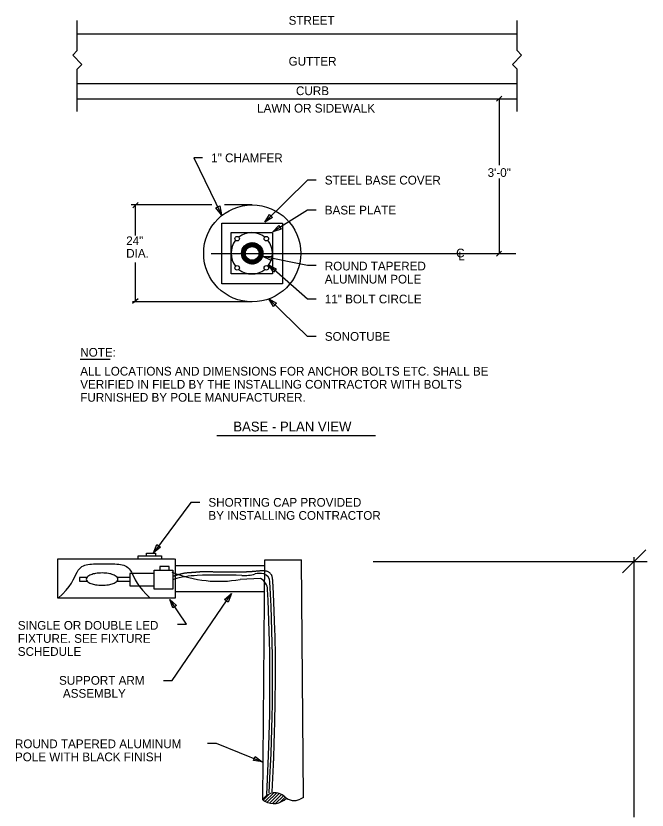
# Model space of a CAD drawing. Extents: x 10112 to 10168, y 10050 to 10179.
# Drawn here: x 10120 to 10168.3, y 10118.7 to 10179.4 of the extents above; entities that cross this region are included whole.
import ezdxf

# ---------------------------------------------------------------- set-up
doc = ezdxf.new("R2010")
doc.units = 0
for name, color, linetype in [('G-ANNO-TEXT', 7, 'Continuous'), ('G-DETL-LINE', 7, 'Continuous'), ('G-DETL-OTLN', 7, 'Continuous'), ('G-DETL-PATT', 7, 'Continuous')]:
    doc.layers.add(name, color=color, linetype=linetype)

msp = doc.modelspace()

# ---------------------------------------------------------------- linework, layer by layer
at = {"layer": 'G-ANNO-TEXT'}
for p, q in [((10157.184, 10173.296), (10156.792, 10172.903)), ((10156.982, 10173.091), (10156.982, 10168.015)), ((10134.303, 10168.58), (10133.637, 10168.58)), ((10133.637, 10168.58), (10135.77, 10164.228)), ((10156.982, 10166.989), (10156.982, 10161.238)), ((10142.321, 10166.873), (10139.076, 10163.664)), ((10142.988, 10166.873), (10142.321, 10166.873)), ((10129.376, 10165.155), (10128.984, 10164.763)), ((10135.018, 10164.983), (10128.862, 10164.983)), ((10129.165, 10164.974), (10129.165, 10162.651)), ((10138.105, 10164.983), (10135.995, 10164.983)), ((10142.321, 10164.581), (10139.677, 10162.912)), ((10142.988, 10164.581), (10142.321, 10164.581)), ((10158.264, 10161.238), (10134.973, 10161.238)), ((10142.321, 10160.342), (10138.925, 10161.033)), ((10157.173, 10161.439), (10156.781, 10161.047)), ((10129.165, 10160.568), (10129.165, 10157.551)), ((10142.321, 10157.781), (10139.339, 10160.394)), ((10142.988, 10160.342), (10142.321, 10160.342)), ((10129.376, 10157.792), (10128.954, 10157.43)), ((10138.105, 10157.562), (10128.959, 10157.562)), ((10142.321, 10154.92), (10139.376, 10157.8)), ((10142.988, 10157.781), (10142.321, 10157.781)), ((10142.988, 10154.92), (10142.321, 10154.92)), ((10124.964, 10153.175), (10127.256, 10153.175)), ((10135.397, 10147.346), (10147.527, 10147.346)), ((10133.424, 10142.217), (10130.559, 10138.375)), ((10134.091, 10142.217), (10133.424, 10142.217)), ((10166.424, 10136.833), (10168.195, 10138.603)), ((10167.31, 10118.148), (10167.31, 10138.036)), ((10147.356, 10137.718), (10168.298, 10137.718)), ((10133.07, 10132.903), (10131.817, 10134.81)), ((10131.983, 10128.612), (10136.511, 10135.252)), ((10132.403, 10132.903), (10133.07, 10132.903)), ((10131.316, 10128.612), (10131.983, 10128.612)), ((10134.682, 10123.803), (10135.348, 10123.803)), ((10135.348, 10123.803), (10138.879, 10122.387))]:
    msp.add_line(p, q, dxfattribs=at)
for points in [[(10135.626, 10164.9), (10135.77, 10164.228), (10135.326, 10164.753)], [(10139.667, 10164.014), (10139.076, 10163.664), (10139.433, 10164.251)], [(10140.33, 10163.127), (10139.677, 10162.912), (10140.152, 10163.409)], [(10139.545, 10160.736), (10138.925, 10161.033), (10139.612, 10161.063)], [(10139.73, 10159.829), (10139.339, 10160.394), (10139.95, 10160.08)], [(10139.736, 10157.214), (10139.376, 10157.8), (10139.969, 10157.453)], [(10131.092, 10138.81), (10130.559, 10138.375), (10130.824, 10139.009)], [(10132.044, 10134.161), (10131.817, 10134.81), (10132.322, 10134.345)], [(10135.997, 10134.795), (10136.511, 10135.252), (10136.273, 10134.607)], [(10138.322, 10122.79), (10138.879, 10122.387), (10138.198, 10122.481)]]:
    msp.add_lwpolyline(points, close=True, dxfattribs=at)
at = {"layer": 'G-DETL-LINE'}
for p, q in [((10124.724, 10178.065), (10158.366, 10178.065)), ((10124.724, 10174.271), (10158.366, 10174.271)), ((10124.724, 10173.091), (10158.366, 10173.091)), ((10136.49, 10159.697), (10136.49, 10162.861)), ((10136.49, 10162.861), (10139.654, 10162.861)), ((10139.654, 10162.861), (10139.654, 10159.697)), ((10137.284, 10161.303), (10138.074, 10162.093)), ((10137.284, 10161.251), (10138.126, 10162.093)), ((10137.287, 10161.201), (10138.176, 10162.09)), ((10137.288, 10161.36), (10138.018, 10162.089)), ((10137.297, 10161.421), (10137.956, 10162.08)), ((10137.893, 10161.756), (10138.222, 10162.085)), ((10137.973, 10161.783), (10138.267, 10162.077)), ((10137.292, 10161.155), (10137.621, 10161.484)), ((10137.312, 10161.488), (10137.889, 10162.064)), ((10137.338, 10161.566), (10137.811, 10162.039)), ((10137.382, 10161.662), (10137.715, 10161.995)), ((10138.038, 10161.796), (10138.309, 10162.068)), ((10138.094, 10161.8), (10138.35, 10162.056)), ((10138.145, 10161.799), (10138.389, 10162.042)), ((10138.191, 10161.793), (10138.426, 10162.028)), ((10138.234, 10161.784), (10138.462, 10162.011)), ((10138.275, 10161.772), (10138.497, 10161.994)), ((10138.312, 10161.757), (10138.53, 10161.975)), ((10138.348, 10161.741), (10138.562, 10161.954)), ((10138.381, 10161.722), (10138.592, 10161.933)), ((10138.412, 10161.701), (10138.622, 10161.91)), ((10138.442, 10161.678), (10138.65, 10161.886)), ((10138.47, 10161.653), (10138.677, 10161.861)), ((10138.495, 10161.627), (10138.703, 10161.834)), ((10138.519, 10161.599), (10138.728, 10161.807)), ((10138.541, 10161.569), (10138.751, 10161.779)), ((10138.562, 10161.537), (10138.773, 10161.748)), ((10138.58, 10161.503), (10138.794, 10161.717)), ((10138.595, 10161.466), (10138.814, 10161.685)), ((10138.609, 10161.428), (10138.833, 10161.652)), ((10138.62, 10161.386), (10138.85, 10161.616)), ((10138.628, 10161.342), (10138.866, 10161.58)), ((10138.631, 10161.241), (10138.893, 10161.502)), ((10138.632, 10161.294), (10138.88, 10161.542)), ((10137.3, 10161.11), (10137.594, 10161.404)), ((10137.31, 10161.068), (10137.581, 10161.339)), ((10137.321, 10161.027), (10137.577, 10161.283)), ((10137.334, 10160.988), (10137.578, 10161.232)), ((10137.349, 10160.951), (10137.584, 10161.186)), ((10137.365, 10160.915), (10137.593, 10161.143)), ((10137.383, 10160.88), (10137.605, 10161.102)), ((10137.402, 10160.847), (10137.62, 10161.065)), ((10137.423, 10160.815), (10137.636, 10161.029)), ((10137.444, 10160.785), (10137.655, 10160.996)), ((10137.467, 10160.755), (10137.676, 10160.965)), ((10137.491, 10160.727), (10137.699, 10160.935)), ((10137.516, 10160.7), (10137.723, 10160.907)), ((10137.542, 10160.674), (10137.75, 10160.882)), ((10137.57, 10160.65), (10137.778, 10160.858)), ((10138.052, 10160.453), (10138.924, 10161.325)), ((10138.103, 10160.452), (10138.926, 10161.275)), ((10138.157, 10160.453), (10138.924, 10161.22)), ((10138.214, 10160.459), (10138.918, 10161.162)), ((10138.278, 10160.47), (10138.907, 10161.099)), ((10138.349, 10160.489), (10138.888, 10161.028)), ((10138.432, 10160.52), (10138.858, 10160.946)), ((10138.569, 10161.022), (10138.92, 10161.373)), ((10138.608, 10161.113), (10138.913, 10161.418)), ((10138.624, 10161.182), (10138.904, 10161.461)), ((10137.599, 10160.626), (10137.808, 10160.836)), ((10137.628, 10160.604), (10137.84, 10160.815)), ((10137.659, 10160.582), (10137.874, 10160.797)), ((10137.692, 10160.563), (10137.911, 10160.781)), ((10137.726, 10160.544), (10137.949, 10160.768)), ((10137.761, 10160.527), (10137.991, 10160.757)), ((10137.797, 10160.511), (10138.035, 10160.749)), ((10137.835, 10160.497), (10138.083, 10160.745)), ((10137.874, 10160.484), (10138.136, 10160.746)), ((10137.916, 10160.473), (10138.195, 10160.753)), ((10137.959, 10160.465), (10138.264, 10160.769)), ((10138.004, 10160.458), (10138.355, 10160.808)), ((10138.542, 10160.577), (10138.799, 10160.834)), ((10139.654, 10159.697), (10136.49, 10159.697)), ((10129.388, 10137.873), (10129.388, 10138.143)), ((10129.388, 10138.143), (10131.173, 10138.143)), ((10130.028, 10138.177), (10130.028, 10138.345)), ((10130.028, 10138.345), (10130.701, 10138.345)), ((10130.701, 10138.345), (10130.701, 10138.143)), ((10131.173, 10138.143), (10131.173, 10137.873)), ((10131.745, 10137.334), (10131.038, 10137.334)), ((10131.038, 10137.334), (10131.038, 10137.098)), ((10131.745, 10137.031), (10131.745, 10137.334)), ((10130.6, 10136.795), (10128.748, 10136.795)), ((10128.748, 10136.795), (10128.748, 10135.852)), ((10130.6, 10135.582), (10130.6, 10137.031)), ((10130.6, 10137.031), (10132.048, 10137.031)), ((10132.048, 10137.031), (10132.048, 10135.582)), ((10124.909, 10136.492), (10124.909, 10136.189)), ((10125.464, 10136.492), (10124.909, 10136.492)), ((10124.909, 10136.189), (10125.499, 10136.189)), ((10127.754, 10136.189), (10128.748, 10136.189)), ((10128.714, 10136.492), (10127.789, 10136.492)), ((10128.748, 10135.852), (10130.6, 10135.852)), ((10132.048, 10135.582), (10130.6, 10135.582))]:
    msp.add_line(p, q, dxfattribs=at)
for points in [[(10123.281, 10134.894), (10123.603, 10135.195), (10123.881, 10135.501), (10124.104, 10135.788), (10124.282, 10136.055), (10124.423, 10136.302), (10124.537, 10136.525), (10124.633, 10136.722), (10124.721, 10136.893), (10124.809, 10137.036), (10124.9, 10137.154), (10124.994, 10137.248), (10125.092, 10137.323), (10125.196, 10137.38), (10125.306, 10137.424), (10125.423, 10137.456), (10125.549, 10137.48), (10125.684, 10137.499), (10125.827, 10137.513), (10125.978, 10137.523), (10126.134, 10137.529), (10126.295, 10137.534), (10126.46, 10137.536), (10126.627, 10137.536), (10126.795, 10137.536), (10126.963, 10137.536), (10127.13, 10137.536), (10127.295, 10137.534), (10127.456, 10137.529), (10127.612, 10137.523), (10127.763, 10137.513), (10127.906, 10137.499), (10128.041, 10137.48), (10128.167, 10137.456), (10128.284, 10137.424), (10128.394, 10137.38), (10128.498, 10137.323), (10128.596, 10137.248), (10128.69, 10137.154), (10128.781, 10137.036), (10128.869, 10136.893), (10128.957, 10136.722), (10129.053, 10136.525), (10129.167, 10136.302), (10129.308, 10136.055), (10129.486, 10135.788), (10129.709, 10135.501), (10129.987, 10135.195), (10130.309, 10134.894)], [(10138.745, 10136.394), (10137.186, 10136.334)], [(10139.225, 10119.892), (10139.345, 10122.833)], [(10139.405, 10120.012), (10139.465, 10121.153)]]:
    msp.add_lwpolyline(points, dxfattribs=at)
for radius in [0.821, 0.528]:
    msp.add_circle((10138.105, 10161.272), radius, dxfattribs=at)
for centre, radius, start, end in [((10138.072, 10161.279), 1.582, 51.23099, 128.76901), ((10138.072, 10161.279), 1.582, 141.23099, 218.76901), ((10138.072, 10161.279), 1.582, 321.23099, 38.76901), ((10138.072, 10161.279), 1.582, 231.23099, 308.76901), ((10126.096, 10135.852), 0.9, 111.26491, 133.21513), ((10126.415, 10135.031), 1.781, 99.15747, 111.26491), ((10126.627, 10133.72), 3.108, 90, 99.15747), ((10126.627, 10133.72), 3.108, 80.84253, 90), ((10126.838, 10135.031), 1.781, 68.73509, 80.84253), ((10127.157, 10135.852), 0.9, 46.78487, 68.73509), ((10134.18, 10129.33), 7.31, 92.30024, 106.63696), ((10135.596, 10094.074), 42.594, 87.69976, 92.30024), ((10137.437, 10139.908), 3.277, 267.69976, 285.72889), ((10138.655, 10135.582), 1.217, 74.27111, 105.72889), ((10138.806, 10136.119), 0.66, 3.01076, 74.2711), ((10125.621, 10136.357), 0.207, 133.21513, 180), ((10125.621, 10136.357), 0.207, 180, 226.78487), ((10126.096, 10136.862), 0.9, 226.78487, 248.73509), ((10126.415, 10137.683), 1.781, 248.73509, 260.84253), ((10126.838, 10137.683), 1.781, 279.15747, 291.26491), ((10127.157, 10136.862), 0.9, 291.26491, 313.21513), ((10127.632, 10136.357), 0.207, 360, 46.78487), ((10127.632, 10136.357), 0.207, 313.21513, 0), ((10138.283, 10135.503), 1.003, 2.85862, 62.57663), ((10126.627, 10138.994), 3.108, 260.84253, 270), ((10126.627, 10138.994), 3.108, 270, 279.15747)]:
    msp.add_arc(centre, radius, start, end, dxfattribs=at)
for centre, major_axis, ratio, start_param, end_param in [((10135.552, 10329.219), (0, 193.028), 0.220109, 3.057124, 3.180061), ((9992.817, 10128.653), (146.851, 0), 0.972426, 6.230638, 6.335733), ((9994.416, 10128.553), (145.049, 0), 0.967642, 6.242419, 6.333078)]:
    msp.add_ellipse(centre, major_axis=major_axis, ratio=ratio, start_param=start_param, end_param=end_param, dxfattribs=at)
msp.add_open_spline([(10139.629, 10120.085), (10139.719, 10121.649), (10139.809, 10124.386), (10139.869, 10127.153), (10139.899, 10130.762), (10139.779, 10134.101), (10139.719, 10135.575), (10139.689, 10136.082), (10139.659, 10136.503), (10139.569, 10136.713), (10139.358, 10136.924), (10138.968, 10137.014), (10137.795, 10136.894), (10136.683, 10136.894), (10135.391, 10136.894), (10134.309, 10136.924), (10133.647, 10136.864), (10132.715, 10136.804), (10132.054, 10136.563)], degree=2, dxfattribs=at)
at = {"layer": 'G-DETL-OTLN'}
for p, q in [((10135.786, 10163.591), (10140.423, 10163.591)), ((10135.786, 10158.954), (10135.786, 10163.591)), ((10140.423, 10163.591), (10140.423, 10158.954)), ((10140.423, 10158.954), (10135.786, 10158.954)), ((10123.25, 10134.894), (10123.25, 10137.898)), ((10123.25, 10137.898), (10132.176, 10137.898)), ((10132.213, 10137.898), (10132.213, 10134.894)), ((10138.91, 10119.465), (10139.067, 10137.825)), ((10139.067, 10137.825), (10141.862, 10137.825)), ((10142.018, 10119.651), (10141.862, 10137.825)), ((10139.028, 10137.379), (10132.213, 10137.379)), ((10138.991, 10135.376), (10132.213, 10135.376)), ((10132.213, 10134.894), (10123.25, 10134.894))]:
    msp.add_line(p, q, dxfattribs=at)
for points in [[(10142.018, 10119.651), (10141.771, 10119.527)], [(10138.91, 10119.465), (10139.072, 10119.372)]]:
    msp.add_lwpolyline(points, dxfattribs=at)
for centre, radius in [((10138.105, 10161.272), 3.71), ((10136.953, 10162.398), 0.172), ((10139.191, 10162.398), 0.172), ((10136.953, 10160.16), 0.172), ((10139.191, 10160.16), 0.172)]:
    msp.add_circle(centre, radius, dxfattribs=at)
for centre, radius, start, end in [((10139.844, 10118.957), 1.063, 45.32138, 151.46519), ((10139.746, 10120.545), 1.352, 240.14708, 316.05653), ((10141.311, 10120.44), 1.022, 225.32138, 296.72464)]:
    msp.add_arc(centre, radius, start, end, dxfattribs=at)
at = {"layer": 'G-DETL-PATT'}
for p, q in [((10124.724, 10176.78), (10124.724, 10179.091)), ((10158.362, 10176.78), (10158.362, 10179.091)), ((10124.724, 10176.78), (10124.38, 10176.436)), ((10158.362, 10176.78), (10158.706, 10176.436)), ((10124.38, 10176.436), (10125.09, 10175.725)), ((10158.706, 10176.436), (10157.996, 10175.725)), ((10125.09, 10175.725), (10124.724, 10175.373)), ((10157.996, 10175.725), (10158.362, 10175.373)), ((10124.724, 10172.117), (10124.724, 10175.373)), ((10158.362, 10172.117), (10158.362, 10175.373)), ((10138.938, 10119.451), (10139.41, 10119.923)), ((10139.1, 10119.371), (10139.723, 10119.995)), ((10139.262, 10119.291), (10139.965, 10119.994)), ((10139.451, 10119.238), (10140.163, 10119.951)), ((10139.653, 10119.199), (10140.344, 10119.89)), ((10139.898, 10119.202), (10140.489, 10119.793)), ((10140.213, 10119.274), (10140.626, 10119.687))]:
    msp.add_line(p, q, dxfattribs=at)

# ---------------------------------------------------------------- texts
at = {"layer": 'G-ANNO-TEXT'}
for s, height, p in [('STREET', 0.6667, (10140.888, 10178.759)), ('GUTTER', 0.6667, (10140.888, 10175.631)), ('CURB', 0.6667, (10141.452, 10173.375)), ('LAWN OR SIDEWALK', 0.66667, (10138.48, 10172.042)), ('1" CHAMFER', 0.6667, (10134.97, 10168.246)), ('3\'-0"', 0.6667, (10156.105, 10167.119)), ('STEEL BASE COVER', 0.66667, (10143.655, 10166.539)), ('BASE PLATE', 0.6667, (10143.655, 10164.248)), ('24"', 0.6667, (10128.472, 10161.906)), ('DIA.', 0.6667, (10128.472, 10160.94)), ('C', 0.667, (10153.697, 10160.966)), ('L', 0.667, (10153.863, 10160.743)), ('ROUND TAPERED ', 0.66667, (10143.655, 10159.967)), ('ALUMINUM POLE ', 0.66667, (10143.655, 10158.967)), ('11" BOLT CIRCLE', 0.66667, (10143.655, 10157.448)), ('SONOTUBE', 0.6667, (10143.655, 10154.587)), ('NOTE:', 0.6667, (10124.96, 10153.371)), ('ALL LOCATIONS AND DIMENSIONS FOR ANCHOR BOLTS ETC. SHALL BE', 0.66667, (10124.96, 10151.926)), ('VERIFIED IN FIELD BY THE INSTALLING CONTRACTOR WITH BOLTS', 0.66667, (10124.96, 10150.926)), ('FURNISHED BY POLE MANUFACTURER.', 0.66667, (10124.96, 10149.926)), ('BASE - PLAN VIEW', 0.75, (10136.662, 10147.652)), ('SHORTING CAP PROVIDED', 0.66667, (10134.758, 10141.895)), ('BY INSTALLING CONTRACTOR', 0.66667, (10134.758, 10140.895)), ('SINGLE OR DOUBLE LED', 0.66667, (10120.184, 10132.487)), ('FIXTURE. SEE FIXTURE', 0.66667, (10120.184, 10131.487)), ('SCHEDULE', 0.6667, (10120.184, 10130.487)), (' SUPPORT ARM', 0.66667, (10123.09, 10128.279)), ('ASSEMBLY', 0.6667, (10123.634, 10127.285)), ('ROUND TAPERED ALUMINUM', 0.66667, (10119.965, 10123.428)), ('POLE WITH BLACK FINISH', 0.66667, (10119.965, 10122.428))]:
    msp.add_text(s, height=height, dxfattribs=at).set_placement(p)

doc.saveas('drawing.dxf')
